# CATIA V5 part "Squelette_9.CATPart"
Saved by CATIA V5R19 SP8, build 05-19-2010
Part number: Squelette_9
Publications: "Plan 8-9 dessus", "C", "Plan 8-9 dessous", "Plan 9-11", "Droite.2", "Point.2", "Droite.1", "Dessus 9", "Point.3", "Droite.3"
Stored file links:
  J:\CFAO_IFMA\Squelette_9.CATPart
  J:\CFAO_IFMA\Squelette.CATProduct
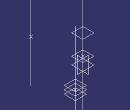
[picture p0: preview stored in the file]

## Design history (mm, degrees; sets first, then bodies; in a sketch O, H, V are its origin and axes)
Parameters
  `Hauteur 8-9` = 30 mm
Set1
  Plane1 "Plan 9-11": linked copy from another document
  Point1 "C": linked copy from another document
Set2
  Plane2 "Dessus 9": type Offset, RefPlane Plane1, Offset 80
  Plane3: type OffsetPt, RefPlane Plane1, RefPoint Point1
  Plane4 "Plan 8-9 dessus": type Offset, RefPlane Plane3, Offset 15 {= `Hauteur 8-9` /2}
  Plane5 "Plan 8-9 dessous": type Offset, RefPlane Plane3, Offset 15 {= `Hauteur 8-9` /2}, reversed
  Point2: type OnPlane, Support Plane1, H 0, V 0, Direction (1, 0, 0)
  Point3: type OnPlane, Support Plane1, RefPoint Point2, H 35, V -170, Direction (1, 0, 0)
  Line1: type Normal, RefPoint Point2, RefSkin Plane1, Start 0, End 20
  Line2: type PtDir, RefPoint Point1, Direction Line1, Start 0, End 20
  Line3: type PtDir, RefPoint Point3, Direction Line1, Start 0, End 20
Body1 (main body)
